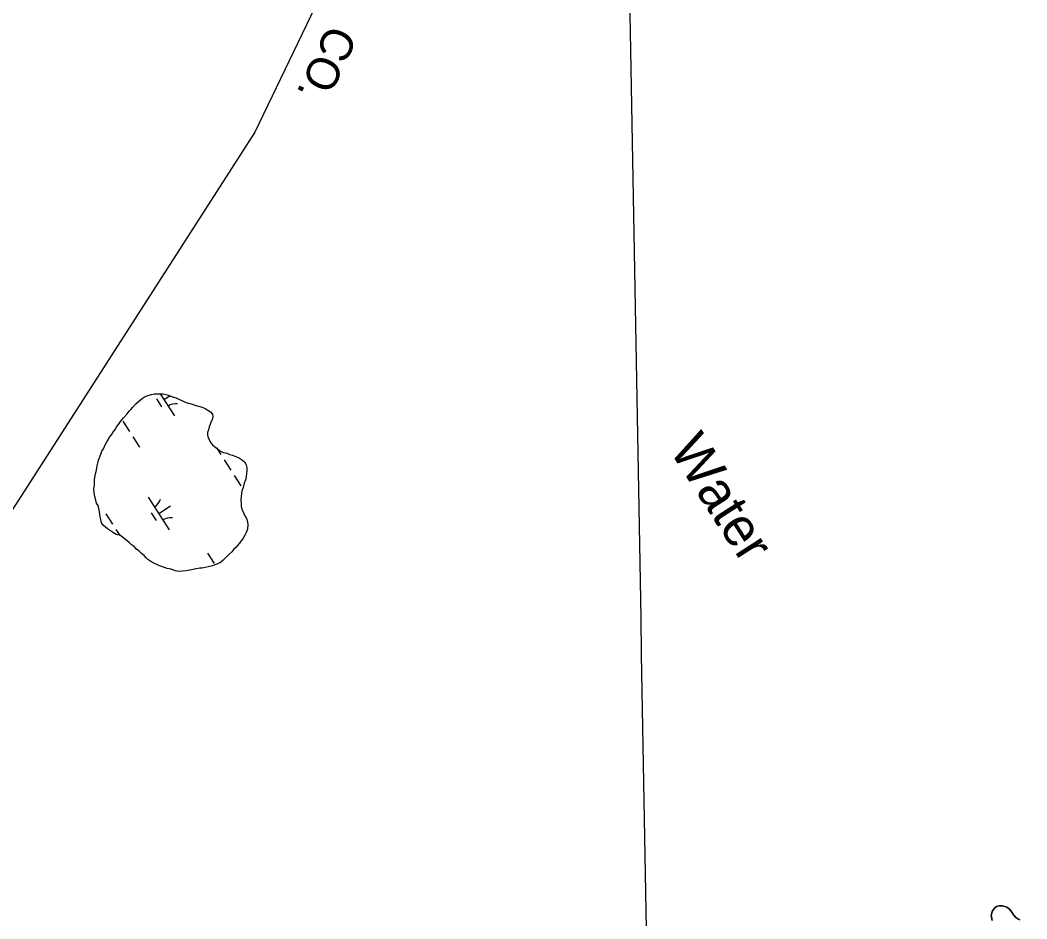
# Model space of a CAD drawing. Extents: x 3937982 to 3958556, y 219448 to 241894.
# Drawn here: x 3945205 to 3946508, y 233760 to 234922 of the extents above; entities that cross this region are included whole.
import ezdxf

# ---------------------------------------------------------------- set-up
doc = ezdxf.new("R2010")
doc.units = 0
for name, color, linetype in [('V-GRID-MAJR', 7, 'Continuous'), ('V-RIVR-IDEN', 7, 'Continuous'), ('V-TOPO-SHOR', 7, 'Continuous'), ('V-UTIL-IDEN', 7, 'Continuous'), ('V-UTIL-LINE', 7, 'Continuous'), ('V-WETL-SWMP', 7, 'Continuous')]:
    doc.layers.add(name, color=color, linetype=linetype)

msp = doc.modelspace()

# ---------------------------------------------------------------- linework, layer by layer
at = {"layer": 'V-GRID-MAJR'}
msp.add_spline([(3946136.867, 227095.12), (3946078.329, 230314.506), (3945968.142, 236374.431), (3945930.73, 238431.955)], degree=3, dxfattribs=at)
at = {"layer": 'V-TOPO-SHOR'}
for points in [[(3945335.261, 234255.621), (3945329.715, 234257.085), (3945326.03, 234258.988), (3945322.358, 234261.818), (3945318.215, 234264.194), (3945315.928, 234266.543), (3945313.177, 234268.898), (3945310.437, 234272.181), (3945309.567, 234276.365), (3945308.688, 234280.086), (3945308.268, 234283.338), (3945307.414, 234288.913), (3945306.097, 234294.496), (3945304.285, 234297.767), (3945303.406, 234301.488), (3945302.077, 234306.143), (3945301.213, 234310.792), (3945300.822, 234316.36), (3945301.342, 234320.528), (3945301.385, 234323.774), (3945301.446, 234328.411), (3945302.929, 234335.345), (3945303.924, 234340.435), (3945304.926, 234345.987), (3945305.895, 234349.219), (3945306.878, 234353.378), (3945309.757, 234360.761), (3945311.205, 234364.914), (3945313.095, 234367.671), (3945315.487, 234373.207), (3945316.917, 234375.969), (3945319.282, 234379.648), (3945320.712, 234382.41), (3945323.542, 234386.083), (3945325.432, 234388.839), (3945328.74, 234393.435), (3945330.167, 234396.198), (3945332.531, 234399.413), (3945335.361, 234403.085), (3945339.138, 234408.135), (3945343.842, 234413.173), (3945346.203, 234416.389), (3945348.552, 234418.676), (3945350.908, 234421.427), (3945355.141, 234426.008), (3945358.43, 234429.211), (3945363.585, 234433.316), (3945366.392, 234435.134), (3945370.589, 234436.932), (3945375.244, 234438.264), (3945378.965, 234439.14), (3945383.139, 234439.085), (3945386.848, 234439.036), (3945390.557, 234438.986), (3945395.638, 234437.528), (3945399.335, 234436.551), (3945402.562, 234435.118), (3945407.18, 234433.666), (3945411.33, 234431.757), (3945414.555, 234430.321), (3945417.783, 234428.888), (3945421.473, 234427.448), (3945424.707, 234426.477), (3945427.941, 234425.507), (3945432.557, 234424.054), (3945436.256, 234423.078), (3945440.872, 234421.626), (3945444.565, 234420.186), (3945448.243, 234417.818), (3945451.462, 234415.92), (3945454.203, 234412.639), (3945454.622, 234409.387), (3945453.639, 234405.225), (3945452.212, 234402.462), (3945451.241, 234399.229), (3945449.814, 234396.466), (3945448.831, 234392.304), (3945447.862, 234389.073), (3945447.813, 234385.364), (3945449.146, 234381.171), (3945451.856, 234375.57), (3945454.143, 234373.221), (3945456.894, 234370.868), (3945460.566, 234368.036), (3945464.696, 234364.734), (3945467.922, 234363.301), (3945473.011, 234362.305), (3945476.233, 234360.409), (3945479.936, 234359.895), (3945485.467, 234357.503), (3945489.154, 234355.6), (3945492.832, 234353.233), (3945495.582, 234350.877), (3945497.852, 234347.138), (3945498.736, 234343.879), (3945498.681, 234339.706), (3945498.161, 234335.54), (3945497.655, 234332.3), (3945497.143, 234328.597), (3945495.22, 234323.522), (3945493.756, 234317.976)], [(3945493.756, 234317.976), (3945492.785, 234314.742), (3945491.808, 234311.046), (3945491.271, 234305.49), (3945490.763, 234302.25), (3945491.155, 234296.679), (3945491.112, 234293.433), (3945492.441, 234288.78), (3945494.698, 234284.113), (3945496.051, 234281.313), (3945498.321, 234277.571), (3945499.656, 234273.379), (3945500.07, 234269.666), (3945499.533, 234264.108), (3945497.616, 234259.496), (3945496.182, 234256.268), (3945493.809, 234252.127), (3945490.501, 234247.533), (3945486.731, 234242.946), (3945484.376, 234240.193), (3945482.027, 234237.908), (3945479.202, 234234.698), (3945474.973, 234230.582), (3945470.275, 234226.007), (3945467.926, 234223.717), (3945464.645, 234220.979), (3945459.978, 234218.722), (3945454.383, 234216.477), (3945448.802, 234215.161), (3945444.616, 234214.288), (3945440.895, 234213.412), (3945437.649, 234213.455), (3945433, 234212.588), (3945426.954, 234211.278), (3945419.98, 234209.977), (3945414.875, 234209.582), (3945410.232, 234209.18), (3945406.072, 234210.163), (3945400.533, 234212.091), (3945395.445, 234213.086), (3945392.218, 234214.52), (3945387.137, 234215.98), (3945382.987, 234217.888), (3945378.375, 234219.805), (3945374.234, 234222.177), (3945370.554, 234224.547), (3945368.268, 234226.896), (3945365.987, 234229.707), (3945362.315, 234232.538), (3945359.112, 234235.827), (3945355.896, 234238.188), (3945352.693, 234241.477), (3945349.021, 234244.308), (3945346.271, 234246.663), (3945335.261, 234255.621)], [(3946498.904, 233758.414), (3946496.125, 233759.851), (3946493.7, 233761.633), (3946490.593, 233764.822), (3946488.191, 233768.352), (3946485.442, 233772.238), (3946481.981, 233775.082), (3946476.404, 233776.557), (3946471.856, 233776.616), (3946468.7, 233775.959), (3946465.867, 233773.546), (3946463.373, 233770.081), (3946461.55, 233764.506), (3946462.857, 233757.494)]]:
    msp.add_lwpolyline(points, dxfattribs=at)
at = {"layer": 'V-UTIL-LINE'}
msp.add_lwpolyline([(3948094.548, 238926.698), (3947981.77, 238738.296), (3948844.302, 237642.921), (3949260.796, 236134.673), (3945931.135, 235655.081), (3945509.058, 234777.685), (3943601.185, 231807.758)], dxfattribs=at)
at = {"layer": 'V-WETL-SWMP'}
for p, q in [((3945386.638, 234439.039), (3945404.948, 234410.593)), ((3945391.417, 234431.615), (3945399.16, 234436.598)), ((3945381.682, 234432.484), (3945388.177, 234422.393)), ((3945338.001, 234403.68), (3945346.661, 234390.226)), ((3945350.991, 234383.499), (3945359.651, 234370.045)), ((3945459.343, 234368.979), (3945464.809, 234360.487)), ((3945469.139, 234353.76), (3945477.799, 234340.306)), ((3945482.129, 234333.579), (3945490.789, 234320.125)), ((3945371.148, 234305.308), (3945398.21, 234263.265)), ((3945384.679, 234284.286), (3945399.815, 234294.029)), ((3945316.282, 234283.911), (3945324.942, 234270.457)), ((3945374.944, 234285.156), (3945381.439, 234275.065)), ((3945329.272, 234263.73), (3945334.335, 234255.864)), ((3945447.849, 234233.023), (3945456.509, 234219.569))]:
    msp.add_line(p, q, dxfattribs=at)
for points in [[(3945335.26, 234255.62), (3945329.715, 234257.085), (3945326.03, 234258.988), (3945322.358, 234261.819), (3945318.216, 234264.193), (3945315.928, 234266.542), (3945313.177, 234268.897), (3945310.438, 234272.18), (3945309.566, 234276.365), (3945308.688, 234280.086), (3945308.268, 234283.338), (3945307.414, 234288.914), (3945306.097, 234294.496), (3945304.285, 234297.766), (3945303.407, 234301.488), (3945302.078, 234306.143), (3945301.212, 234310.791), (3945300.822, 234316.361), (3945301.341, 234320.528), (3945301.384, 234323.774), (3945301.446, 234328.41), (3945302.929, 234335.346), (3945303.924, 234340.434), (3945304.925, 234345.986), (3945305.895, 234349.219), (3945306.878, 234353.379), (3945309.758, 234360.761), (3945311.204, 234364.915), (3945313.096, 234367.672), (3945315.488, 234373.206), (3945316.916, 234375.969), (3945319.283, 234379.647), (3945320.711, 234382.411), (3945323.542, 234386.083), (3945325.433, 234388.84), (3945328.74, 234393.434), (3945330.168, 234396.197), (3945332.53, 234399.412), (3945335.361, 234403.084), (3945339.137, 234408.135), (3945343.842, 234413.174), (3945346.203, 234416.389), (3945348.552, 234418.676), (3945350.907, 234421.427), (3945355.141, 234426.009), (3945358.43, 234429.211), (3945363.585, 234433.316), (3945366.392, 234435.134), (3945370.589, 234436.933), (3945375.244, 234438.263), (3945378.966, 234439.141), (3945383.138, 234439.085), (3945386.848, 234439.036), (3945390.557, 234438.987), (3945395.638, 234437.528), (3945399.335, 234436.552), (3945402.562, 234435.118), (3945407.18, 234433.666), (3945411.329, 234431.756), (3945414.556, 234430.322), (3945417.783, 234428.888), (3945421.474, 234427.448), (3945424.707, 234426.477), (3945427.94, 234425.507), (3945432.558, 234424.055), (3945436.255, 234423.078), (3945440.873, 234421.626), (3945444.564, 234420.185), (3945448.242, 234417.818), (3945451.463, 234415.92), (3945454.202, 234412.638), (3945454.623, 234409.386), (3945453.64, 234405.226), (3945452.212, 234402.462), (3945451.242, 234399.229), (3945449.814, 234396.466), (3945448.831, 234392.305), (3945447.861, 234389.072), (3945447.812, 234385.363), (3945449.147, 234381.171), (3945451.855, 234375.571), (3945454.143, 234373.222), (3945456.894, 234370.867), (3945460.566, 234368.036), (3945464.696, 234364.735), (3945467.923, 234363.301), (3945473.011, 234362.306), (3945476.232, 234360.408), (3945479.935, 234359.895), (3945485.468, 234357.503), (3945489.153, 234355.6), (3945492.831, 234353.232), (3945495.582, 234350.877), (3945497.851, 234347.137), (3945498.736, 234343.879), (3945498.68, 234339.706), (3945498.161, 234335.54), (3945497.655, 234332.3), (3945497.142, 234328.597), (3945495.22, 234323.522), (3945493.755, 234317.977)], [(3945493.755, 234317.977), (3945492.785, 234314.743), (3945491.808, 234311.046), (3945491.271, 234305.489), (3945490.764, 234302.249), (3945491.154, 234296.679), (3945491.111, 234293.434), (3945492.44, 234288.779), (3945494.697, 234284.112), (3945496.051, 234281.312), (3945498.32, 234277.572), (3945499.656, 234273.38), (3945500.07, 234269.665), (3945499.533, 234264.107), (3945497.617, 234259.495), (3945496.183, 234256.268), (3945493.809, 234252.126), (3945490.502, 234247.533), (3945486.731, 234242.946), (3945484.376, 234240.194), (3945482.027, 234237.907), (3945479.202, 234234.698), (3945474.974, 234230.581), (3945470.276, 234226.006), (3945467.927, 234223.718), (3945464.645, 234220.979), (3945459.978, 234218.723), (3945454.383, 234216.478), (3945448.801, 234215.161), (3945444.616, 234214.289), (3945440.894, 234213.411), (3945437.649, 234213.454), (3945433, 234212.588), (3945426.954, 234211.277), (3945419.981, 234209.978), (3945414.875, 234209.582), (3945410.232, 234209.18), (3945406.072, 234210.163), (3945400.532, 234212.091), (3945395.445, 234213.086), (3945392.218, 234214.52), (3945387.136, 234215.979), (3945382.988, 234217.889), (3945378.376, 234219.805), (3945374.234, 234222.178), (3945370.555, 234224.546), (3945368.268, 234226.895), (3945365.986, 234229.707), (3945362.314, 234232.538), (3945359.112, 234235.827), (3945355.897, 234238.188), (3945352.694, 234241.477), (3945349.022, 234244.308), (3945346.271, 234246.663), (3945335.26, 234255.62)], [(3946462.856, 233757.493), (3946461.55, 233764.507), (3946463.373, 233770.081), (3946465.868, 233773.546), (3946468.699, 233775.958), (3946471.856, 233776.616), (3946476.404, 233776.556), (3946481.982, 233775.082), (3946485.443, 233772.237), (3946488.19, 233768.352), (3946490.593, 233764.822), (3946493.699, 233761.632), (3946496.124, 233759.851), (3946498.904, 233758.414)]]:
    msp.add_lwpolyline(points, dxfattribs=at)
for centre, start, end in [((3945406.567, 234408.517), 81.996677, 123.540335), ((3945369.929, 234307.641), 301.99668, 343.540338), ((3945399.829, 234261.189), 81.996677, 123.540335)]:
    msp.add_arc(centre, 17.623, start, end, dxfattribs=at)

# ---------------------------------------------------------------- texts
at = {"layer": 'V-RIVR-IDEN'}
msp.add_text('Water', height=49.9999, rotation=302.768556, dxfattribs=at).set_placement((3946044.335, 234366.801))
at = {"layer": 'V-UTIL-IDEN'}
msp.add_text('SHELL OIL CO. ', height=41.99992, rotation=244.886309, dxfattribs=at).set_placement((3945731.93, 235190.11))

doc.saveas('drawing.dxf')
